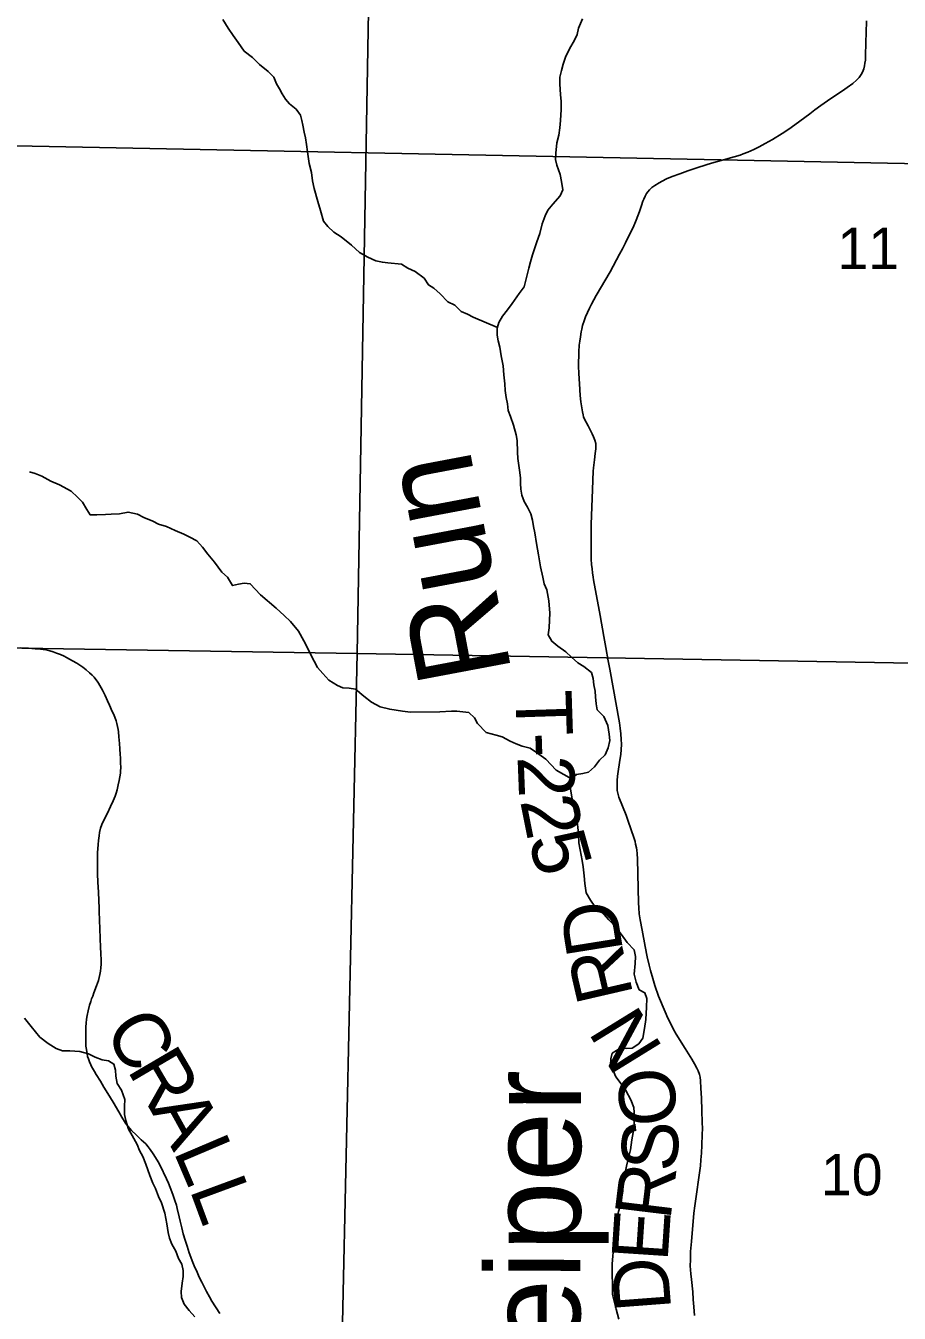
# Model space of a CAD drawing. Extents: x 0 to 34, y 0 to 22.
# Drawn here: x 21.94 to 22.822, y 17.999 to 19.3 of the extents above; entities that cross this region are included whole.
import ezdxf

# ---------------------------------------------------------------- set-up
doc = ezdxf.new("R2010")
doc.units = 0
for name, color, linetype in [('GM_X_Corporation', 7, 'Continuous'), ('GM_X_Minor_River', 7, 'Continuous'), ('GM_X_Minor_River_Text', 7, 'Continuous'), ('GM_X_Section_Text', 7, 'Continuous'), ('GM_X_Township_Road', 7, 'Continuous'), ('GM_X_Township_Road_Text', 7, 'Continuous')]:
    doc.layers.add(name, color=color, linetype=linetype)

msp = doc.modelspace()

# ---------------------------------------------------------------- linework, layer by layer
at = {"layer": 'GM_X_Corporation'}
for points in [[(25.4, 19.0068), (25.4, 20.4), (21.2921, 20.4), (21.2757, 19.6748), (21.2742, 19.6071), (21.273, 19.5535), (21.2652, 19.1913), (21.5297, 19.1865), (21.7744, 19.1817), (21.8956, 19.1793), (22.6423, 19.1645), (23.3329, 19.1508), (23.5499, 19.1465), (23.786, 19.1434), (24.169, 19.1418), (24.3186, 19.1409), (24.3186, 19.0261), (24.5766, 19.0222)], [(22.2928, 19.6778), (22.2749, 18.6656), (21.2582, 18.6819), (21.2769, 19.6922)], [(22.2928, 19.6778), (23.3052, 19.6529), (23.3004, 18.648), (22.2749, 18.6656)], [(21.2582, 18.6819), (22.2749, 18.6656), (22.2529, 17.6514), (21.2422, 17.6682)], [(22.2749, 18.6656), (23.3004, 18.648), (23.2763, 17.6399), (22.2529, 17.6514)]]:
    msp.add_lwpolyline(points, close=True, dxfattribs=at)
msp.add_lwpolyline([(25.4, 14.4307), (25.4, 19.0068), (24.5766, 19.0222), (24.3186, 19.0261), (24.3186, 19.1409), (24.169, 19.1418), (23.786, 19.1434), (23.5499, 19.1465), (23.3329, 19.1508), (22.6423, 19.1645), (21.8956, 19.1793), (21.7744, 19.1817), (21.5297, 19.1865), (21.2652, 19.1913), (20.8916, 19.1966), (20.254, 19.2058), (20.2471, 18.8539), (20.2208, 16.9558), (20.1987, 15.2691)], dxfattribs=at)
at = {"layer": 'GM_X_Minor_River'}
for points in [[(22.4167, 18.995), (22.3921, 19.0057), (22.3864, 19.0087), (22.3799, 19.0112), (22.3737, 19.0176), (22.3665, 19.0209), (22.3588, 19.0292), (22.3523, 19.0348), (22.3469, 19.0381), (22.3427, 19.0449), (22.3335, 19.0516), (22.3262, 19.0549), (22.3197, 19.059), (22.3061, 19.0603), (22.3004, 19.061), (22.2939, 19.0624), (22.2859, 19.0661), (22.2772, 19.0709), (22.2691, 19.0784), (22.2588, 19.0866), (22.2515, 19.0915), (22.2454, 19.0971), (22.2411, 19.1027), (22.2379, 19.1133), (22.2351, 19.1224), (22.2315, 19.1357), (22.2299, 19.1433), (22.2287, 19.1516), (22.2266, 19.1607), (22.2249, 19.1725), (22.2237, 19.1801), (22.2228, 19.1869), (22.2216, 19.1926), (22.22, 19.1995), (22.2192, 19.2044), (22.2176, 19.2097), (22.2133, 19.2157), (22.2068, 19.221), (22.2026, 19.2258), (22.1991, 19.2311), (22.1964, 19.2364), (22.1936, 19.2413), (22.1909, 19.2481), (22.1851, 19.2537), (22.1763, 19.2608), (22.1694, 19.268), (22.161, 19.2743), (22.1548, 19.283), (22.1498, 19.2901), (22.1447, 19.2976), (22.1393, 19.3063)], [(22.4812, 19.2548), (22.483, 19.2613), (22.4855, 19.2682), (22.4896, 19.2774), (22.494, 19.2847), (22.497, 19.2912), (22.4984, 19.2974), (22.5024, 19.3069)], [(22.4919, 18.5205), (22.4907, 18.5269), (22.4899, 18.5326), (22.4905, 18.5383), (22.4965, 18.5434), (22.5029, 18.5446), (22.5086, 18.5459), (22.5146, 18.5513), (22.5198, 18.5578), (22.5254, 18.5632), (22.5283, 18.5705), (22.5301, 18.5778), (22.5296, 18.5842), (22.528, 18.593), (22.5241, 18.602), (22.5175, 18.6088), (22.5163, 18.6149), (22.5158, 18.6221), (22.5154, 18.6278), (22.5141, 18.6339), (22.5133, 18.6403), (22.5117, 18.6464), (22.504, 18.6527), (22.4979, 18.6564), (22.4914, 18.662), (22.4856, 18.6673), (22.4776, 18.6733), (22.4715, 18.6781), (22.468, 18.6845), (22.469, 18.6918), (22.4693, 18.6994), (22.4695, 18.7066), (22.4686, 18.7188), (22.4665, 18.7302), (22.4638, 18.7362), (22.4626, 18.7427), (22.4601, 18.7533), (22.4581, 18.7654), (22.456, 18.7768), (22.4543, 18.7878), (22.4531, 18.7939), (22.4519, 18.8004), (22.4503, 18.8068), (22.4471, 18.8136), (22.4436, 18.8193), (22.4413, 18.8257), (22.4401, 18.8318), (22.44, 18.8375), (22.4399, 18.8432), (22.439, 18.8508), (22.4373, 18.8629), (22.4369, 18.869), (22.4367, 18.8808), (22.4355, 18.8865), (22.4327, 18.8963), (22.4299, 18.9051), (22.4275, 18.9111), (22.4267, 18.918), (22.4255, 18.9244), (22.4246, 18.9316), (22.4241, 18.9381), (22.4232, 18.9472), (22.4223, 18.9563), (22.4203, 18.9666), (22.419, 18.9753), (22.4174, 18.9817), (22.4162, 18.9874), (22.4165, 18.9943), (22.4179, 19), (22.4216, 19.0066), (22.4268, 19.0131), (22.4316, 19.0193), (22.4387, 19.0293), (22.4435, 19.0362), (22.446, 19.0457), (22.4485, 19.0549), (22.45, 19.0614), (22.4521, 19.0687), (22.4565, 19.0817), (22.4594, 19.0901), (22.4619, 19.1), (22.4648, 19.1081), (22.4674, 19.1138), (22.4726, 19.1196), (22.48, 19.1281), (22.4826, 19.1342), (22.4813, 19.1426), (22.4801, 19.1498), (22.4765, 19.1592), (22.4753, 19.1649), (22.4756, 19.1714), (22.4766, 19.1817), (22.4788, 19.1893), (22.4798, 19.197), (22.4804, 19.2042), (22.481, 19.2153), (22.4809, 19.2236), (22.4804, 19.2305), (22.4795, 19.2411), (22.4798, 19.248), (22.4812, 19.2548)], [(22.4913, 18.539), (22.476, 18.548), (22.4656, 18.5589), (22.4561, 18.5656), (22.4496, 18.5701), (22.4416, 18.5722), (22.4355, 18.5744), (22.4294, 18.577), (22.4214, 18.5814), (22.4153, 18.5832), (22.4054, 18.5858), (22.3966, 18.5951), (22.3935, 18.6008), (22.3877, 18.606), (22.3756, 18.6074), (22.3703, 18.6073), (22.3585, 18.6067), (22.329, 18.6063), (22.3207, 18.6073), (22.3078, 18.6094), (22.2983, 18.6119), (22.2895, 18.6167), (22.2818, 18.6227), (22.2734, 18.6298), (22.2669, 18.6308), (22.2605, 18.6311), (22.2552, 18.6333), (22.2464, 18.6389), (22.2402, 18.6456), (22.2348, 18.6516), (22.2317, 18.6581), (22.2278, 18.6652), (22.2247, 18.6713), (22.2212, 18.6785), (22.2157, 18.6883), (22.2076, 18.698), (22.2011, 18.704), (22.1931, 18.7115), (22.1773, 18.725), (22.167, 18.7362), (22.1609, 18.7369), (22.1552, 18.7357), (22.1492, 18.7344), (22.1441, 18.7427), (22.1384, 18.748), (22.131, 18.7581), (22.1241, 18.766), (22.1187, 18.7732), (22.1129, 18.7796), (22.1061, 18.7833), (22.1, 18.7862), (22.0912, 18.7899), (22.0824, 18.7939), (22.0744, 18.7965), (22.0687, 18.7994), (22.0596, 18.8031), (22.0531, 18.8064), (22.0436, 18.8086), (22.0349, 18.8069), (22.0266, 18.8064), (22.0209, 18.8063), (22.0122, 18.8058), (22.0054, 18.8057), (22.0019, 18.8113), (21.9976, 18.8185), (21.9926, 18.8238), (21.9861, 18.8297), (21.9743, 18.836), (21.9655, 18.8397), (21.9564, 18.8449), (21.9499, 18.8475), (21.9442, 18.8493)], [(22.5394, 17.993), (22.5366, 18.0032), (22.5346, 18.0112), (22.533, 18.018), (22.5325, 18.0488), (22.5332, 18.0572), (22.5338, 18.064), (22.5341, 18.0736), (22.5351, 18.0797), (22.5357, 18.0888), (22.5389, 18.1018), (22.5411, 18.1098), (22.5421, 18.1163), (22.5432, 18.1224), (22.5435, 18.1289), (22.5452, 18.1392), (22.547, 18.1476), (22.5495, 18.1575), (22.5509, 18.1644), (22.5523, 18.1743), (22.5537, 18.1819), (22.5547, 18.1907), (22.555, 18.1972), (22.5544, 18.2071), (22.5513, 18.2146), (22.5462, 18.2241), (22.5416, 18.2309), (22.5362, 18.238), (22.5334, 18.2444), (22.5307, 18.2501), (22.531, 18.2562), (22.5324, 18.2619), (22.5414, 18.2674), (22.5471, 18.2667), (22.5528, 18.2668), (22.5596, 18.2715), (22.5636, 18.2772), (22.565, 18.2868), (22.5664, 18.2959), (22.5673, 18.3085), (22.5676, 18.3173), (22.5656, 18.3229), (22.5599, 18.3259), (22.5568, 18.3335), (22.5547, 18.3418), (22.5557, 18.3525), (22.556, 18.3597), (22.5548, 18.3662), (22.5478, 18.3737), (22.5417, 18.3823), (22.5363, 18.3891), (22.5293, 18.3966), (22.5216, 18.4052), (22.5151, 18.4101), (22.5105, 18.4165), (22.5062, 18.424), (22.5049, 18.4335), (22.5041, 18.4411), (22.5032, 18.4502), (22.5023, 18.4567), (22.5003, 18.4673), (22.499, 18.4745), (22.4985, 18.4825), (22.4977, 18.4901), (22.4964, 18.4992), (22.4944, 18.5064), (22.4928, 18.5148), (22.4919, 18.5205)], [(22.1111, 17.9955), (22.1054, 18.0019), (22.1004, 18.0083), (22.0976, 18.0151), (22.0971, 18.0212), (22.0981, 18.0296), (22.0992, 18.0361), (22.0991, 18.0422), (22.0979, 18.0486), (22.0947, 18.0546), (22.092, 18.0618), (22.0877, 18.069), (22.0854, 18.0751), (22.0841, 18.0807), (22.0829, 18.0895), (22.0808, 18.1001), (22.0773, 18.1107), (22.0745, 18.1171), (22.0714, 18.1251), (22.0686, 18.1307), (22.0655, 18.1383), (22.0616, 18.1497), (22.0584, 18.1576), (22.0553, 18.1636), (22.0529, 18.1697), (22.0479, 18.1788), (22.044, 18.1852), (22.0412, 18.1939), (22.04, 18.1999), (22.0399, 18.2083), (22.0402, 18.2152), (22.037, 18.2246), (22.0327, 18.2314), (22.0311, 18.2386), (22.031, 18.2447), (22.0294, 18.2508), (22.0237, 18.2541), (22.0176, 18.2552), (22.0104, 18.2577), (22.0035, 18.2614), (21.9948, 18.2636), (21.9849, 18.2642), (21.9773, 18.2644), (21.9709, 18.2666), (21.9628, 18.2718), (21.9544, 18.2782), (21.9459, 18.2887), (21.939, 18.2973)]]:
    msp.add_lwpolyline(points, dxfattribs=at)
at = {"layer": 'GM_X_Township_Road'}
for points in [[(22.6558, 19.1676), (22.6616, 19.1694), (22.6647, 19.1705), (22.6695, 19.1724), (22.6755, 19.175), (22.6811, 19.1777), (22.687, 19.1809), (22.6945, 19.1849), (22.7042, 19.1911), (22.7108, 19.1956), (22.717, 19.1998), (22.727, 19.2073), (22.732, 19.2111), (22.7372, 19.215), (22.7431, 19.2195), (22.7498, 19.2241), (22.7595, 19.2306), (22.765, 19.2342), (22.7699, 19.2375), (22.7756, 19.2417), (22.7794, 19.2451), (22.7819, 19.2478), (22.784, 19.2508), (22.7853, 19.2532), (22.7865, 19.2564), (22.7873, 19.2595), (22.7878, 19.2623), (22.7882, 19.2652), (22.7884, 19.2693), (22.7888, 19.2833), (22.789, 19.2928), (22.7892, 19.3051)], [(22.5123, 18.8877), (22.5105, 18.891), (22.5081, 18.8956), (22.5046, 18.9026), (22.5037, 18.905), (22.5031, 18.9068), (22.5024, 18.9098), (22.5014, 18.916), (22.501, 18.9199), (22.5003, 18.9265), (22.4994, 18.9382), (22.4987, 18.9487), (22.4985, 18.9562), (22.4987, 18.9705), (22.4992, 18.9774), (22.4997, 18.9812), (22.5004, 18.9856), (22.5012, 18.9909), (22.5018, 18.9935), (22.5027, 18.9973), (22.5042, 19.0019), (22.5057, 19.0058), (22.5096, 19.0148), (22.5116, 19.0188), (22.5165, 19.0276), (22.5305, 19.0515), (22.5399, 19.0692), (22.5428, 19.0745), (22.5458, 19.0806), (22.5498, 19.0883), (22.552, 19.0929), (22.5544, 19.0979), (22.5562, 19.102), (22.5592, 19.1095), (22.5604, 19.1132), (22.5622, 19.1184), (22.5636, 19.1227), (22.5645, 19.1249), (22.5659, 19.1279), (22.5672, 19.1305), (22.5684, 19.1322), (22.5702, 19.1342), (22.5726, 19.1364), (22.5757, 19.1387), (22.58, 19.1414), (22.583, 19.1431), (22.5873, 19.1452), (22.5931, 19.1476), (22.6008, 19.1505), (22.609, 19.1534), (22.6179, 19.1564), (22.6274, 19.1594), (22.6327, 19.161), (22.639, 19.1629), (22.6449, 19.1644), (22.6558, 19.1676)], [(22.6156, 17.9969), (22.6149, 18.0056), (22.6144, 18.0129), (22.6138, 18.0208), (22.6125, 18.0331), (22.6118, 18.0391), (22.6113, 18.0469), (22.6115, 18.0531), (22.6116, 18.0616), (22.6126, 18.0715), (22.615, 18.1004), (22.6159, 18.1075), (22.6216, 18.1481), (22.6222, 18.1542), (22.6227, 18.1607), (22.6232, 18.1689), (22.6235, 18.1798), (22.6236, 18.1858), (22.6235, 18.1917), (22.6231, 18.2041), (22.6227, 18.2163), (22.6222, 18.2266), (22.6217, 18.2338), (22.6213, 18.2376), (22.6207, 18.2403), (22.6193, 18.2439), (22.618, 18.2466), (22.6156, 18.2511), (22.6129, 18.2557), (22.6113, 18.2585), (22.6063, 18.2665), (22.5973, 18.281), (22.5941, 18.2864), (22.5913, 18.2921), (22.5887, 18.2974), (22.5859, 18.3036), (22.5794, 18.3196), (22.5756, 18.3304), (22.5735, 18.3373), (22.5711, 18.3455), (22.5698, 18.3508), (22.568, 18.3593), (22.5658, 18.3696), (22.5627, 18.3861), (22.5608, 18.3965), (22.5599, 18.4028), (22.5594, 18.4089), (22.5591, 18.4138), (22.5581, 18.4578), (22.5577, 18.4638), (22.5574, 18.467), (22.557, 18.4694), (22.5562, 18.473), (22.5556, 18.4757), (22.554, 18.4808), (22.5521, 18.4867), (22.5481, 18.4982), (22.5466, 18.5023), (22.5394, 18.5206), (22.5386, 18.5234), (22.5377, 18.5272), (22.5374, 18.5307), (22.5376, 18.5374), (22.538, 18.5419), (22.5386, 18.5465), (22.54, 18.5555), (22.5412, 18.564), (22.5416, 18.5685), (22.5418, 18.574), (22.5417, 18.5789), (22.5412, 18.5846), (22.5406, 18.5903), (22.5398, 18.5958), (22.5301, 18.65), (22.5285, 18.6583), (22.5261, 18.6717), (22.5241, 18.6829), (22.5205, 18.7041), (22.5138, 18.7402), (22.5133, 18.743), (22.5125, 18.7471), (22.5122, 18.7512), (22.5117, 18.7558), (22.5114, 18.7612), (22.5112, 18.7705), (22.5114, 18.7962), (22.5125, 18.8313), (22.5133, 18.8498), (22.5135, 18.8534), (22.5146, 18.8613), (22.5155, 18.8677), (22.5159, 18.8726), (22.5161, 18.8756), (22.5159, 18.8779), (22.5151, 18.8814), (22.5138, 18.8845), (22.5123, 18.8877)], [(22.0144, 18.408), (22.0136, 18.4246), (22.013, 18.4347), (22.0127, 18.4431), (22.0126, 18.4522), (22.0128, 18.4642), (22.0134, 18.4728), (22.0137, 18.4767), (22.0144, 18.4815), (22.0148, 18.4849), (22.0159, 18.4894), (22.0172, 18.493), (22.0196, 18.4981), (22.0227, 18.5044), (22.026, 18.511), (22.0287, 18.5169), (22.0305, 18.5215), (22.0316, 18.5245), (22.0327, 18.5281), (22.0337, 18.533), (22.0347, 18.5374), (22.0354, 18.5412), (22.0359, 18.5448), (22.0361, 18.5473), (22.0362, 18.5501), (22.0361, 18.5555), (22.036, 18.5602), (22.0357, 18.5637), (22.0353, 18.5695), (22.0349, 18.5747), (22.0343, 18.5816), (22.0338, 18.5866), (22.0335, 18.5888), (22.033, 18.592), (22.0323, 18.5949), (22.0315, 18.5977), (22.0291, 18.6041), (22.0277, 18.6072), (22.0249, 18.6134), (22.0229, 18.6178), (22.0204, 18.6233), (22.0178, 18.6286), (22.0137, 18.6359), (22.0123, 18.6379), (22.011, 18.6396), (22.0093, 18.6417), (22.0074, 18.6438), (22.0048, 18.6463), (22.0013, 18.6493), (21.998, 18.652), (21.997, 18.6527), (21.9918, 18.6558), (21.9876, 18.6584), (21.9816, 18.6617), (21.979, 18.663), (21.9754, 18.6646), (21.9713, 18.6662), (21.9679, 18.6673), (21.9645, 18.6683), (21.9604, 18.6693), (21.9553, 18.67), (21.9499, 18.6705), (21.9429, 18.671), (21.9351, 18.6713)], [(22.1363, 17.9988), (22.1283, 18.0112), (22.1257, 18.0157), (22.1229, 18.021), (22.1203, 18.0259), (22.118, 18.0305), (22.1155, 18.0355), (22.1133, 18.0406), (22.1103, 18.0469), (22.1083, 18.052), (22.1069, 18.0559), (22.1054, 18.0601), (22.1032, 18.0668), (22.1012, 18.0731), (22.0994, 18.0792), (22.0978, 18.0854), (22.0961, 18.0922), (22.0952, 18.0965), (22.0933, 18.1048), (22.0924, 18.1082), (22.0909, 18.1132), (22.0892, 18.1181), (22.0879, 18.1219), (22.0845, 18.1304), (22.0825, 18.1349), (22.0759, 18.1484), (22.0739, 18.152), (22.0713, 18.1566), (22.0689, 18.1603), (22.066, 18.1645), (22.0638, 18.1673), (22.0614, 18.1702), (22.0569, 18.1745), (22.0518, 18.1793), (22.0472, 18.1837), (22.0451, 18.186), (22.042, 18.1898), (22.041, 18.1913), (22.0373, 18.1974), (22.0342, 18.2025), (22.0284, 18.2124), (22.0233, 18.2211), (22.0193, 18.2277), (22.0158, 18.2335), (22.0115, 18.2404), (22.0098, 18.2434), (22.0068, 18.2485), (22.0061, 18.2501), (22.0047, 18.2532), (22.0035, 18.2563), (22.0028, 18.2586), (22.0022, 18.2614), (22.0015, 18.2657), (22.0011, 18.2689), (22.0009, 18.2719), (22.001, 18.2885), (22.0012, 18.2922), (22.0017, 18.2963), (22.0022, 18.2999), (22.0032, 18.3046), (22.0048, 18.3104), (22.0059, 18.3141), (22.0068, 18.3167), (22.0079, 18.3195), (22.0091, 18.3227), (22.0118, 18.3298), (22.0137, 18.3353), (22.0145, 18.3382), (22.0152, 18.3413), (22.0157, 18.3447), (22.0161, 18.348), (22.0164, 18.3519), (22.0165, 18.3554), (22.0161, 18.3631), (22.0159, 18.3687), (22.015, 18.3874), (22.0145, 18.4049), (22.0144, 18.408)]]:
    msp.add_lwpolyline(points, dxfattribs=at)

# ---------------------------------------------------------------- texts
at = {"layer": 'GM_X_Minor_River_Text'}
for s, rotation, p in [('Run', 100.694, (22.4313, 18.6461)), ('Leiper', 89.7662, (22.4998, 17.8926))]:
    msp.add_text(s, height=0.09468, rotation=rotation, dxfattribs=at).set_placement(p)
at = {"layer": 'GM_X_Section_Text'}
for s, p in [('11', (22.76, 19.0542)), ('10', (22.7433, 18.1183))]:
    msp.add_text(s, height=0.04186, rotation=0, dxfattribs=at).set_placement(p)
at = {"layer": 'GM_X_Township_Road_Text'}
for s, rotation, p in [('T', 271.8646, (22.4347, 18.6278)), ('-', 271.9299, (22.4361, 18.5852)), ('2', 272.2365, (22.4369, 18.5616)), ('2', 281.3127, (22.4394, 18.5169)), ('5', 285.6701, (22.4474, 18.478)), ('D', 99.1126, (22.5437, 18.3652)), ('R', 103.0546, (22.5541, 18.3208)), ('C', 300.4289, (22.0184, 18.2854)), ('N', 121.6985, (22.5847, 18.2664)), ('R', 300.4115, (22.042, 18.2452)), ('O', 97.1103, (22.5997, 18.1919)), ('A', 298.9555, (22.0655, 18.2053)), ('S', 85.6259, (22.5971, 18.1412)), ('L', 293.0669, (22.089, 18.1629)), ('L', 290.2716, (22.1054, 18.1245)), ('R', 83.0749, (22.5912, 18.0922)), ('E', 86.1788, (22.5884, 18.0506)), ('D', 94.3811, (22.5922, 18.0029))]:
    msp.add_text(s, height=0.0568, rotation=rotation, dxfattribs=at).set_placement(p)

doc.saveas('drawing.dxf')
